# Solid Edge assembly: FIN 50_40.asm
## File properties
Title: Zylinder
Author: bmolnar
Template: iso assembly.asm
Last saved by: bmolnar
Revision: 12
Application: Solid Edge
Username: bmolnar
Dokumentum tartalom típus: 1
Document Number: FIN 50/40
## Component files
Kit_1.par
Profilrohr.par
Kit_2.par
Kolbenstange.par
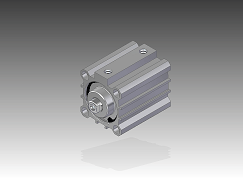
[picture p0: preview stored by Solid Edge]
